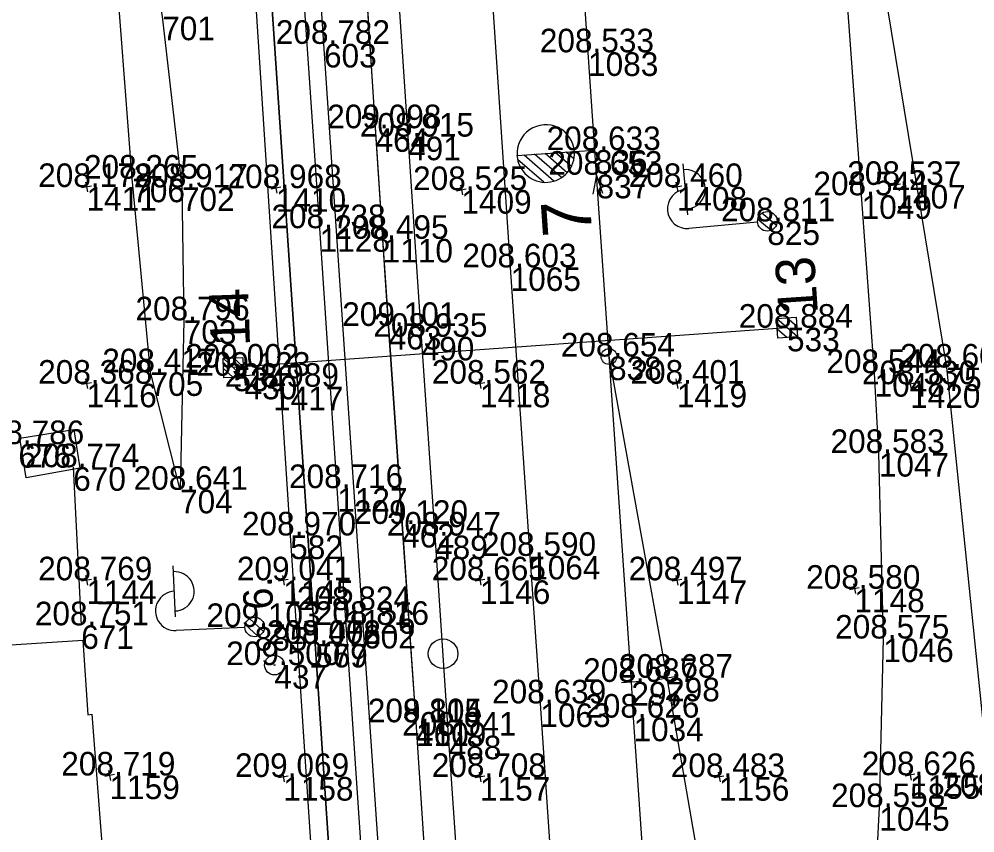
# Model space of a CAD drawing. Extents: x -556590 to -554855, y -1137918 to -1135717.
# Drawn here: x -554953.42 to -554904.86, y -1137642.84 to -1137601.46 of the extents above; entities that cross this region are included whole.
import ezdxf

# ---------------------------------------------------------------- set-up
doc = ezdxf.new("R2010")
doc.units = 0
for name, color, linetype in [('Vrstva 1', 7, 'Continuous'), ('Vrstva 11', 7, 'Continuous'), ('Vrstva 14', 7, 'Continuous'), ('Vrstva 17', 7, 'Continuous'), ('Vrstva 2', 7, 'Continuous'), ('Vrstva 23', 7, 'Continuous'), ('Vrstva 25', 7, 'Continuous'), ('Vrstva 49', 7, 'Continuous'), ('Vrstva 51', 7, 'Continuous'), ('Vrstva 60', 7, 'Continuous'), ('Vrstva 61', 7, 'Continuous'), ('Vrstva 7', 7, 'Continuous')]:
    doc.layers.add(name, color=color, linetype=linetype)

msp = doc.modelspace()

# ---------------------------------------------------------------- linework, layer by layer
at = {"layer": 'Vrstva 1'}
for points in [[(-554924.167, -1137608.122), (-554924.511, -1137603.151), (-554925.397, -1137590.18), (-554926.328, -1137576.586), (-554927.274, -1137562.665), (-554928.265, -1137548.068), (-554929.313, -1137532.88), (-554930.318, -1137518.241), (-554930.722, -1137512.299)], [(-554917.975, -1137769.552), (-554918.963, -1137754.815), (-554920.086, -1137737.896), (-554921.053, -1137723.548), (-554921.381, -1137719.023), (-554921.495, -1137717.207), (-554921.933, -1137710.655), (-554922.979, -1137695.094), (-554924.253, -1137675.995), (-554925.623, -1137655.572), (-554926.937, -1137636.258), (-554927.454, -1137628.755), (-554928.446, -1137614.083), (-554929.485, -1137598.553), (-554930.559, -1137582.57), (-554931.667, -1137566.254), (-554932.879, -1137548.591), (-554934.309, -1137529.922)], [(-554927.452, -1137770.473), (-554928.449, -1137755.712), (-554929.562, -1137739.23), (-554930.556, -1137724.715), (-554930.9, -1137719.598), (-554931.034, -1137717.552), (-554931.481, -1137710.736), (-554932.204, -1137700.023), (-554932.469, -1137696.167), (-554932.595, -1137694.151), (-554933.117, -1137686.686), (-554934.152, -1137671.759), (-554934.854, -1137661.232), (-554935.125, -1137657.229), (-554935.687, -1137648.862), (-554936.859, -1137631.513), (-554937.258, -1137625.309), (-554938.149, -1137612.094), (-554939.101, -1137598.034), (-554940.12, -1137582.921), (-554941.144, -1137567.775), (-554942.217, -1137552.225), (-554943.433, -1137536.043)], [(-554912.12, -1137717.809), (-554912.248, -1137715.711), (-554912.365, -1137713.967), (-554912.887, -1137706.122), (-554912.119, -1137688.223), (-554912.088, -1137687.497), (-554911.853, -1137682.02), (-554911.103, -1137668.018), (-554910.285, -1137652.829), (-554909.709, -1137641.532), (-554909.501, -1137632.959), (-554909.737, -1137623.526), (-554909.95, -1137619.461), (-554910.61, -1137610.419), (-554911.54, -1137597.875), (-554912.594, -1137582.977), (-554913.612, -1137568.149), (-554914.538, -1137554.794), (-554914.947, -1137549.002), (-554915.779, -1137537.195)], [(-554930.884, -1137648.475), (-554931.599, -1137637.897), (-554932.285, -1137627.724), (-554932.968, -1137617.617), (-554933.656, -1137607.436), (-554934.37, -1137596.756), (-554935.06, -1137586.479), (-554935.745, -1137576.286), (-554936.45, -1137565.815), (-554937.151, -1137555.461), (-554937.161, -1137555.34), (-554937.226, -1137554.403), (-554937.848, -1137545.575)], [(-554913.245, -1137768.913), (-554914.617, -1137748.553), (-554915.822, -1137730.843), (-554916.674, -1137718.248), (-554916.793, -1137716.482), (-554918.211, -1137695.564), (-554919.703, -1137673.774), (-554920.652, -1137659.545), (-554921.142, -1137652.458), (-554922.204, -1137636.981), (-554922.31, -1137635.165), (-554923.446, -1137618.62), (-554924.08, -1137609.374), (-554924.167, -1137608.122)], [(-554912.12, -1137717.809), (-554912.365, -1137713.967), (-554912.887, -1137706.122), (-554914.03, -1137688.41), (-554914.961, -1137674.68), (-554915.997, -1137663.144), (-554917.083, -1137654.934), (-554918.513, -1137646.457), (-554920.492, -1137634.952), (-554923.446, -1137618.62), (-554924.08, -1137609.374), (-554924.167, -1137608.122)]]:
    msp.add_lwpolyline(points, dxfattribs=at)
at = {"layer": 'Vrstva 11'}
for p, q in [((-554913.874, -1137617.62), (-554914.936, -1137616.693)), ((-554913.907, -1137617.094), (-554914.411, -1137616.654)), ((-554914.404, -1137617.155), (-554942.537, -1137619.182)), ((-554914.403, -1137617.656), (-554914.901, -1137617.222)), ((-554942.023, -1137619.665), (-554943.054, -1137618.702)), ((-554942.038, -1137619.138), (-554942.527, -1137618.681)), ((-554942.553, -1137619.683), (-554943.036, -1137619.232))]:
    msp.add_line(p, q, dxfattribs=at)
for points in [[(-554914.869, -1137617.688), (-554914.937, -1137616.69), (-554913.939, -1137616.622), (-554913.871, -1137617.62)], [(-554943.02, -1137619.699), (-554943.054, -1137618.699), (-554942.054, -1137618.665), (-554942.02, -1137619.665)]]:
    msp.add_lwpolyline(points, close=True, dxfattribs=at)
at = {"layer": 'Vrstva 14'}
for points in [[(-554943.664, -1137554.571), (-554944.223, -1137554.644), (-554943.027, -1137575.6), (-554941.448, -1137599.994), (-554939.649, -1137627.718), (-554937.668, -1137657.599), (-554936.721, -1137657.499)], [(-554936.721, -1137657.499), (-554936.819, -1137656.544), (-554938.386, -1137633.229), (-554940.9, -1137595.934), (-554942.999, -1137564.635), (-554943.625, -1137555.587), (-554943.664, -1137554.571)], [(-554943.664, -1137554.571), (-554943.625, -1137555.587), (-554942.999, -1137564.635), (-554940.9, -1137595.934), (-554938.386, -1137633.229), (-554936.819, -1137656.544), (-554936.721, -1137657.499)], [(-554926.758, -1137768.121), (-554928.518, -1137741.891), (-554929.98, -1137719.751), (-554930.124, -1137717.521), (-554931.584, -1137696.135), (-554931.726, -1137694.002), (-554933.296, -1137671.213), (-554933.974, -1137661.145), (-554934.241, -1137656.955), (-554935.944, -1137632.264), (-554937.931, -1137602.72), (-554939.802, -1137574.881), (-554941.104, -1137554.789), (-554938.902, -1137554.586)], [(-554931.889, -1137658.069), (-554931.922, -1137657.332), (-554933.251, -1137637.218), (-554934.945, -1137612.635), (-554937.297, -1137576.773), (-554938.774, -1137555.612), (-554938.902, -1137554.586)], [(-554929.334, -1137695.867), (-554929.441, -1137693.923), (-554929.5, -1137693.042), (-554930, -1137690), (-554930.173, -1137683.019), (-554930.845, -1137672.941), (-554931.537, -1137662.834), (-554931.685, -1137660.824), (-554931.78, -1137659.935), (-554931.889, -1137658.069), (-554931.922, -1137657.332), (-554932.592, -1137647.264), (-554933.251, -1137637.218), (-554933.96, -1137627.13), (-554934.647, -1137617.064), (-554935.312, -1137607.011), (-554935.955, -1137596.939), (-554936.647, -1137586.834), (-554937.297, -1137576.773), (-554937.979, -1137566.689), (-554938.774, -1137555.612), (-554938.902, -1137554.586)]]:
    msp.add_lwpolyline(points, dxfattribs=at)
at = {"layer": 'Vrstva 17'}
msp.add_line((-554950.674, -1137624.247), (-554950.266, -1137632.287), dxfattribs=at)
at = {"layer": 'Vrstva 2'}
for p, q in [((-554928.123, -1137608.398), (-554925.203, -1137608.197)), ((-554926.247, -1137609.697), (-554927.767, -1137608.373)), ((-554925.868, -1137609.523), (-554927.232, -1137608.336)), ((-554925.577, -1137609.273), (-554926.695, -1137608.299)), ((-554925.36, -1137608.958), (-554926.159, -1137608.263)), ((-554925.228, -1137608.569), (-554925.622, -1137608.226)), ((-554925.203, -1137608.197), (-554924.167, -1137608.122)), ((-554928.123, -1137608.399), (-554928.123, -1137608.398)), ((-554926.758, -1137609.756), (-554928.094, -1137608.593)), ((-554920.492, -1137634.952), (-554923.446, -1137618.62)), ((-554920.985, -1137635.038), (-554919.999, -1137634.866)), ((-554922.809, -1137635.199), (-554921.811, -1137635.131))]:
    msp.add_line(p, q, dxfattribs=at)
for points in [[(-554922.31, -1137635.165), (-554923.446, -1137618.62), (-554924.08, -1137609.374), (-554924.167, -1137608.122)], [(-554923.758, -1137610.321), (-554924.08, -1137609.374), (-554924.274, -1137610.355)]]:
    msp.add_lwpolyline(points, dxfattribs=at)
msp.add_circle((-554923.446, -1137618.62), 0.4, dxfattribs=at)
for centre, radius, start, end in [((-554926.662, -1137608.296), 1.462, 3.892, 184.3615), ((-554926.663, -1137608.298), 1.464, 183.9815, 3.9424)]:
    msp.add_arc(centre, radius, start, end, dxfattribs=at)
at = {"layer": 'Vrstva 23'}
for points in [[(-554950.641, -1137622.334), (-554950.339, -1137624.298), (-554953.069, -1137624.795), (-554953.387, -1137622.773), (-554950.641, -1137622.334)], [(-554950.193, -1137633.042), (-554949.93, -1137636.837), (-554949.734, -1137636.811), (-554949.116, -1137644.697), (-554953.161, -1137645.16), (-554953.215, -1137644.474), (-554955.465, -1137644.636), (-554955.801, -1137640.052), (-554959.441, -1137640.444), (-554959.384, -1137641.245), (-554960.199, -1137641.347), (-554960.283, -1137640.446), (-554960.725, -1137640.53), (-554960.906, -1137638.764), (-554960.202, -1137638.686), (-554960.254, -1137637.647), (-554957.306, -1137637.41), (-554957.496, -1137633.522), (-554950.193, -1137633.042)]]:
    msp.add_lwpolyline(points, dxfattribs=at)
at = {"layer": 'Vrstva 25'}
for p, q in [((-554919.449, -1137611.411), (-554919.685, -1137608.821)), ((-554915.213, -1137612.208), (-554915.889, -1137611.645)), ((-554914.945, -1137611.943), (-554915.681, -1137611.331)), ((-554915.9, -1137611.79), (-554919.386, -1137612.108)), ((-554945.481, -1137631.856), (-554945.599, -1137629.259)), ((-554941.006, -1137632.593), (-554941.713, -1137631.947)), ((-554941.952, -1137632.397), (-554945.449, -1137632.556)), ((-554941.285, -1137632.845), (-554941.935, -1137632.252))]:
    msp.add_line(p, q, dxfattribs=at)
for centre in [(-554915.402, -1137611.745), (-554941.453, -1137632.374)]:
    msp.add_circle(centre, 0.5, dxfattribs=at)
for centre, start, end in [((-554919.555, -1137610.115), 274.5002, 95.9053), ((-554919.476, -1137611.112), 95.2028, 275.2028), ((-554945.527, -1137630.557), 271.8984, 93.3036), ((-554945.494, -1137631.557), 92.601, 272.601)]:
    msp.add_arc(centre, 1, start, end, dxfattribs=at)
at = {"layer": 'Vrstva 49'}
for p, q in [((-554950.047, -1137609.754), (-554949.953, -1137610.246)), ((-554940.423, -1137609.812), (-554940.329, -1137610.304)), ((-554920.047, -1137609.754), (-554919.953, -1137610.246)), ((-554908.936, -1137609.647), (-554908.842, -1137610.139)), ((-554949.754, -1137609.953), (-554950.246, -1137610.047)), ((-554940.13, -1137610.011), (-554940.622, -1137610.105)), ((-554930.701, -1137610.108), (-554931.193, -1137610.202)), ((-554930.994, -1137609.909), (-554930.9, -1137610.401)), ((-554919.754, -1137609.953), (-554920.246, -1137610.047)), ((-554908.643, -1137609.846), (-554909.135, -1137609.94)), ((-554949.754, -1137619.953), (-554950.246, -1137620.047)), ((-554950.047, -1137619.754), (-554949.953, -1137620.246)), ((-554940.563, -1137619.911), (-554940.469, -1137620.403)), ((-554929.754, -1137619.953), (-554930.246, -1137620.047)), ((-554930.047, -1137619.754), (-554929.953, -1137620.246)), ((-554919.754, -1137619.953), (-554920.246, -1137620.047)), ((-554920.047, -1137619.754), (-554919.953, -1137620.246)), ((-554907.899, -1137619.981), (-554908.391, -1137620.075)), ((-554908.192, -1137619.782), (-554908.098, -1137620.274)), ((-554940.27, -1137620.11), (-554940.762, -1137620.204)), ((-554950.047, -1137629.754), (-554949.953, -1137630.246)), ((-554940.047, -1137629.754), (-554939.953, -1137630.246)), ((-554930.047, -1137629.754), (-554929.953, -1137630.246)), ((-554920.047, -1137629.754), (-554919.953, -1137630.246)), ((-554949.754, -1137629.953), (-554950.246, -1137630.047)), ((-554939.754, -1137629.953), (-554940.246, -1137630.047)), ((-554929.754, -1137629.953), (-554930.246, -1137630.047)), ((-554919.754, -1137629.953), (-554920.246, -1137630.047)), ((-554911.022, -1137630.182), (-554910.928, -1137630.674)), ((-554910.729, -1137630.381), (-554911.221, -1137630.475)), ((-554948.582, -1137639.877), (-554949.074, -1137639.971)), ((-554948.875, -1137639.678), (-554948.781, -1137640.17)), ((-554939.754, -1137639.953), (-554940.246, -1137640.047)), ((-554940.047, -1137639.754), (-554939.953, -1137640.246)), ((-554929.754, -1137639.953), (-554930.246, -1137640.047)), ((-554930.047, -1137639.754), (-554929.953, -1137640.246)), ((-554917.608, -1137639.957), (-554918.1, -1137640.051)), ((-554917.901, -1137639.758), (-554917.807, -1137640.25)), ((-554907.902, -1137639.863), (-554908.394, -1137639.957)), ((-554908.195, -1137639.664), (-554908.101, -1137640.156))]:
    msp.add_line(p, q, dxfattribs=at)
for points in [[(-554951.38, -1137516.096), (-554950.362, -1137520.761), (-554949.334, -1137537.69), (-554948.595, -1137552.125), (-554948.14, -1137568.191), (-554946.72, -1137585.029), (-554946.477, -1137591.556), (-554947.039, -1137593.937), (-554947.027, -1137596.272), (-554946.152, -1137601.334), (-554945.152, -1137610.021), (-554945.058, -1137616.778), (-554945.247, -1137625.395)], [(-554945.247, -1137625.395), (-554946.746, -1137619.421), (-554947.672, -1137609.573), (-554948.428, -1137599.781), (-554948.83, -1137593.698), (-554949.629, -1137579.724), (-554951.035, -1137566.737), (-554950.648, -1137554.742), (-554950.163, -1137542.828), (-554950.887, -1137529.142), (-554951.325, -1137520.784), (-554951.38, -1137516.096)]]:
    msp.add_lwpolyline(points, dxfattribs=at)
at = {"layer": 'Vrstva 51'}
msp.add_lwpolyline([(-554923.958, -1137439.154), (-554921.384, -1137460.492), (-554920.249, -1137473.563), (-554918.745, -1137491.257), (-554915.318, -1137516.028), (-554914.46, -1137526.509), (-554912.018, -1137566.83), (-554909.54, -1137599.474), (-554906.296, -1137619.179), (-554904.054, -1137640.988), (-554902.007, -1137663.515), (-554901.204, -1137677.928), (-554900.627, -1137681.481), (-554898.957, -1137685.66), (-554896.57, -1137689.296), (-554893.815, -1137691.613), (-554889.437, -1137693.47), (-554883.069, -1137697.253), (-554880.009, -1137699.781), (-554876.436, -1137704.84), (-554873.989, -1137710.204), (-554871.95, -1137718.337), (-554870.137, -1137731.24), (-554867.796, -1137750.715)], dxfattribs=at)
at = {"layer": 'Vrstva 60'}
for p, q in [((-554937.931, -1137602.72), (-554937.931, -1137602.72)), ((-554924.511, -1137603.151), (-554924.511, -1137603.151)), ((-554935.312, -1137607.011), (-554935.312, -1137607.011)), ((-554933.656, -1137607.436), (-554933.656, -1137607.436)), ((-554924.167, -1137608.122), (-554924.167, -1137608.122)), ((-554947.672, -1137609.573), (-554947.672, -1137609.573)), ((-554924.08, -1137609.374), (-554924.08, -1137609.374)), ((-554950, -1137610), (-554950, -1137610)), ((-554945.152, -1137610.021), (-554945.152, -1137610.021)), ((-554940.376, -1137610.058), (-554940.376, -1137610.058)), ((-554930.947, -1137610.155), (-554930.947, -1137610.155)), ((-554920, -1137610), (-554920, -1137610)), ((-554908.889, -1137609.893), (-554908.889, -1137609.893)), ((-554910.61, -1137610.419), (-554910.61, -1137610.419)), ((-554915.402, -1137611.745), (-554915.402, -1137611.745)), ((-554938.149, -1137612.094), (-554938.149, -1137612.094)), ((-554934.945, -1137612.635), (-554934.945, -1137612.635)), ((-554928.446, -1137614.083), (-554928.446, -1137614.083)), ((-554945.058, -1137616.778), (-554945.058, -1137616.778)), ((-554934.647, -1137617.064), (-554934.647, -1137617.064)), ((-554914.404, -1137617.155), (-554914.404, -1137617.155)), ((-554932.968, -1137617.617), (-554932.968, -1137617.617)), ((-554923.446, -1137618.62), (-554923.446, -1137618.62)), ((-554946.746, -1137619.421), (-554946.746, -1137619.421)), ((-554942.537, -1137619.182), (-554942.537, -1137619.182)), ((-554909.95, -1137619.461), (-554909.95, -1137619.461)), ((-554906.296, -1137619.179), (-554906.296, -1137619.179)), ((-554950, -1137620), (-554950, -1137620)), ((-554941.969, -1137619.595), (-554941.969, -1137619.595)), ((-554930, -1137620), (-554930, -1137620)), ((-554920, -1137620), (-554920, -1137620)), ((-554908.145, -1137620.028), (-554908.145, -1137620.028)), ((-554940.516, -1137620.157), (-554940.516, -1137620.157)), ((-554909.737, -1137623.526), (-554909.737, -1137623.526)), ((-554950.674, -1137624.247), (-554950.674, -1137624.247)), ((-554937.258, -1137625.309), (-554937.258, -1137625.309)), ((-554945.247, -1137625.395), (-554945.247, -1137625.395)), ((-554933.96, -1137627.13), (-554933.96, -1137627.13)), ((-554939.649, -1137627.718), (-554939.649, -1137627.718)), ((-554932.285, -1137627.724), (-554932.285, -1137627.724)), ((-554927.454, -1137628.755), (-554927.454, -1137628.755)), ((-554950, -1137630), (-554950, -1137630)), ((-554940, -1137630), (-554940, -1137630)), ((-554930, -1137630), (-554930, -1137630)), ((-554920, -1137630), (-554920, -1137630)), ((-554910.975, -1137630.428), (-554910.975, -1137630.428)), ((-554936.859, -1137631.513), (-554936.859, -1137631.513)), ((-554950.266, -1137632.287), (-554950.266, -1137632.287)), ((-554941.453, -1137632.374), (-554941.453, -1137632.374)), ((-554935.944, -1137632.264), (-554935.944, -1137632.264)), ((-554909.501, -1137632.959), (-554909.501, -1137632.959)), ((-554938.386, -1137633.229), (-554938.386, -1137633.229)), ((-554938.386, -1137633.229), (-554938.386, -1137633.229)), ((-554940.45, -1137634.31), (-554940.45, -1137634.31)), ((-554920.492, -1137634.952), (-554920.492, -1137634.952)), ((-554922.31, -1137635.165), (-554922.31, -1137635.165)), ((-554926.937, -1137636.258), (-554926.937, -1137636.258)), ((-554922.204, -1137636.981), (-554922.204, -1137636.981)), ((-554933.251, -1137637.218), (-554933.251, -1137637.218)), ((-554933.251, -1137637.218), (-554933.251, -1137637.218)), ((-554931.599, -1137637.897), (-554931.599, -1137637.897)), ((-554948.828, -1137639.924), (-554948.828, -1137639.924)), ((-554908.148, -1137639.91), (-554908.148, -1137639.91)), ((-554940, -1137640), (-554940, -1137640)), ((-554930, -1137640), (-554930, -1137640)), ((-554917.854, -1137640.004), (-554917.854, -1137640.004)), ((-554909.709, -1137641.532), (-554909.709, -1137641.532))]:
    msp.add_line(p, q, dxfattribs=at)
at = {"layer": 'Vrstva 7'}
for p, q in [((-554942.003, -1137619.096), (-554941.935, -1137620.094)), ((-554941.47, -1137619.561), (-554942.468, -1137619.629)), ((-554940.4, -1137634.31), (-554940.5, -1137634.31))]:
    msp.add_line(p, q, dxfattribs=at)
for centre, radius in [((-554931.88, -1137633.732), 0.75), ((-554940.45, -1137634.31), 0.5)]:
    msp.add_circle(centre, radius, dxfattribs=at)

# ---------------------------------------------------------------- texts
at = {"layer": 'Vrstva 11'}
for s, rotation, p in [('13', 93.866, (-554912.827, -1137616.436)), ('14', 91.9449, (-554941.688, -1137618.089))]:
    msp.add_text(s, height=2, rotation=rotation, dxfattribs=at).set_placement(p)
at = {"layer": 'Vrstva 2'}
msp.add_text('7', height=2.5, rotation=93.9619, dxfattribs=at).set_placement((-554924.298, -1137612.432))
at = {"layer": 'Vrstva 25'}
msp.add_text('6.', height=1.5, rotation=92.601, dxfattribs=at).set_placement((-554940.508, -1137631.455))
at = {"layer": 'Vrstva 60'}
for s, p in [('701', (-554946.152, -1137602.534)), ('603', (-554937.931, -1137603.92)), ('1083', (-554924.511, -1137604.351)), ('464', (-554935.312, -1137608.211)), ('491', (-554933.656, -1137608.636)), ('836', (-554924.167, -1137609.322)), ('837', (-554924.08, -1137610.574)), ('706', (-554947.672, -1137610.773)), ('1411', (-554950, -1137611.2)), ('702', (-554945.152, -1137611.221)), ('1410', (-554940.376, -1137611.258)), ('1409', (-554930.947, -1137611.355)), ('1408', (-554920, -1137611.2)), ('1407', (-554908.889, -1137611.093)), ('1049', (-554910.61, -1137611.619)), ('825', (-554915.402, -1137612.945)), ('1128', (-554938.149, -1137613.294)), ('1110', (-554934.945, -1137613.835)), ('1065', (-554928.446, -1137615.283)), ('703', (-554945.058, -1137617.978)), ('463', (-554934.647, -1137618.264)), ('490', (-554932.968, -1137618.817)), ('533', (-554914.404, -1137618.355)), ('838', (-554923.446, -1137619.82)), ('705', (-554946.746, -1137620.621)), ('534', (-554942.537, -1137620.382)), ('1048', (-554909.95, -1137620.661)), ('752', (-554906.296, -1137620.379)), ('1416', (-554950, -1137621.2)), ('430', (-554941.969, -1137620.795)), ('1418', (-554930, -1137621.2)), ('1419', (-554920, -1137621.2)), ('1420', (-554908.145, -1137621.228)), ('1417', (-554940.516, -1137621.357)), ('676', (-554953.461, -1137624.273)), ('1047', (-554909.737, -1137624.726)), ('670', (-554950.674, -1137625.447)), ('704', (-554945.247, -1137626.595)), ('1127', (-554937.258, -1137626.509)), ('462', (-554933.96, -1137628.33)), ('582', (-554939.649, -1137628.918)), ('489', (-554932.285, -1137628.924)), ('1064', (-554927.454, -1137629.955)), ('1144', (-554950, -1137631.2)), ('1145', (-554940, -1137631.2)), ('1146', (-554930, -1137631.2)), ('1147', (-554920, -1137631.2)), ('1148', (-554910.975, -1137631.628)), ('1126', (-554936.859, -1137632.713)), ('671', (-554950.266, -1137633.487)), ('885', (-554941.453, -1137633.574)), ('602', (-554935.944, -1137633.464)), ('1046', (-554909.501, -1137634.159)), ('569', (-554938.386, -1137634.429)), ('577', (-554938.386, -1137634.429)), ('437', (-554940.45, -1137635.51)), ('298', (-554920.492, -1137636.152)), ('297', (-554922.31, -1137636.365)), ('1063', (-554926.937, -1137637.458)), ('1034', (-554922.204, -1137638.181)), ('461', (-554933.251, -1137638.418)), ('1109', (-554933.251, -1137638.418)), ('488', (-554931.599, -1137639.097)), ('1159', (-554948.828, -1137641.124)), ('1155', (-554908.148, -1137641.11)), ('1158', (-554940, -1137641.2)), ('1157', (-554930, -1137641.2)), ('1156', (-554917.854, -1137641.204)), ('1045', (-554909.709, -1137642.732))]:
    msp.add_text(s, height=1.2, dxfattribs=at).set_placement(p)
at = {"layer": 'Vrstva 61'}
for s, p in [('208.782', (-554940.379, -1137602.72)), ('208.533', (-554926.963, -1137603.151)), ('209.098', (-554937.766, -1137607.011)), ('208.915', (-554936.112, -1137607.436)), ('208.633', (-554926.619, -1137608.122)), ('208.265', (-554950.128, -1137609.573)), ('208.653', (-554926.532, -1137609.374)), ('208.178', (-554952.454, -1137610)), ('208.917', (-554947.604, -1137610.021)), ('208.968', (-554942.83, -1137610.058)), ('208.460', (-554922.451, -1137610)), ('208.537', (-554911.341, -1137609.893)), ('208.525', (-554933.403, -1137610.155)), ('208.544', (-554913.061, -1137610.419)), ('208.811', (-554917.759, -1137611.745)), ('208.738', (-554940.603, -1137612.094)), ('208.495', (-554937.401, -1137612.635)), ('208.603', (-554930.898, -1137614.083)), ('208.796', (-554947.51, -1137616.778)), ('209.101', (-554937.004, -1137617.064)), ('208.884', (-554916.855, -1137617.155)), ('208.935', (-554935.424, -1137617.617)), ('208.654', (-554925.897, -1137618.62)), ('209.002', (-554944.985, -1137619.182)), ('208.601', (-554908.653, -1137619.179)), ('208.417', (-554949.198, -1137619.421)), ('209.123', (-554944.421, -1137619.595)), ('208.544', (-554912.401, -1137619.461)), ('208.368', (-554952.454, -1137620)), ('208.989', (-554942.97, -1137620.157)), ('208.562', (-554932.448, -1137620)), ('208.401', (-554922.357, -1137620)), ('208.530', (-554910.596, -1137620.028)), ('208.786', (-554955.913, -1137623.073)), ('208.583', (-554912.189, -1137623.526)), ('208.774', (-554953.125, -1137624.247)), ('208.641', (-554947.604, -1137625.395)), ('208.716', (-554939.71, -1137625.309)), ('209.120', (-554936.411, -1137627.13)), ('208.970', (-554942.1, -1137627.718)), ('208.947', (-554934.737, -1137627.724)), ('208.590', (-554929.905, -1137628.755)), ('208.769', (-554952.454, -1137630)), ('209.041', (-554942.357, -1137630)), ('208.665', (-554932.456, -1137630)), ('208.497', (-554922.452, -1137630)), ('208.580', (-554913.426, -1137630.428)), ('208.824', (-554939.31, -1137631.513)), ('208.751', (-554952.623, -1137632.287)), ('209.103', (-554943.905, -1137632.374)), ('208.816', (-554938.396, -1137632.264)), ('208.478', (-554940.84, -1137633.229)), ('209.002', (-554940.834, -1137633.229)), ('208.575', (-554911.957, -1137632.959)), ('209.500', (-554942.901, -1137634.31)), ('208.687', (-554924.762, -1137635.165)), ('208.687', (-554922.944, -1137634.952)), ('208.639', (-554929.391, -1137636.258)), ('208.815', (-554935.707, -1137637.218)), ('209.104', (-554935.702, -1137637.218)), ('208.626', (-554924.656, -1137636.981)), ('208.941', (-554933.956, -1137637.897)), ('208.719', (-554951.282, -1137639.924)), ('209.069', (-554942.454, -1137640)), ('208.708', (-554932.454, -1137640)), ('208.483', (-554920.306, -1137640.004)), ('208.626', (-554910.6, -1137639.91)), ('208.593', (-554906.506, -1137640.988)), ('208.558', (-554912.163, -1137641.532))]:
    msp.add_text(s, height=1.2, dxfattribs=at).set_placement(p)

doc.saveas('drawing.dxf')
